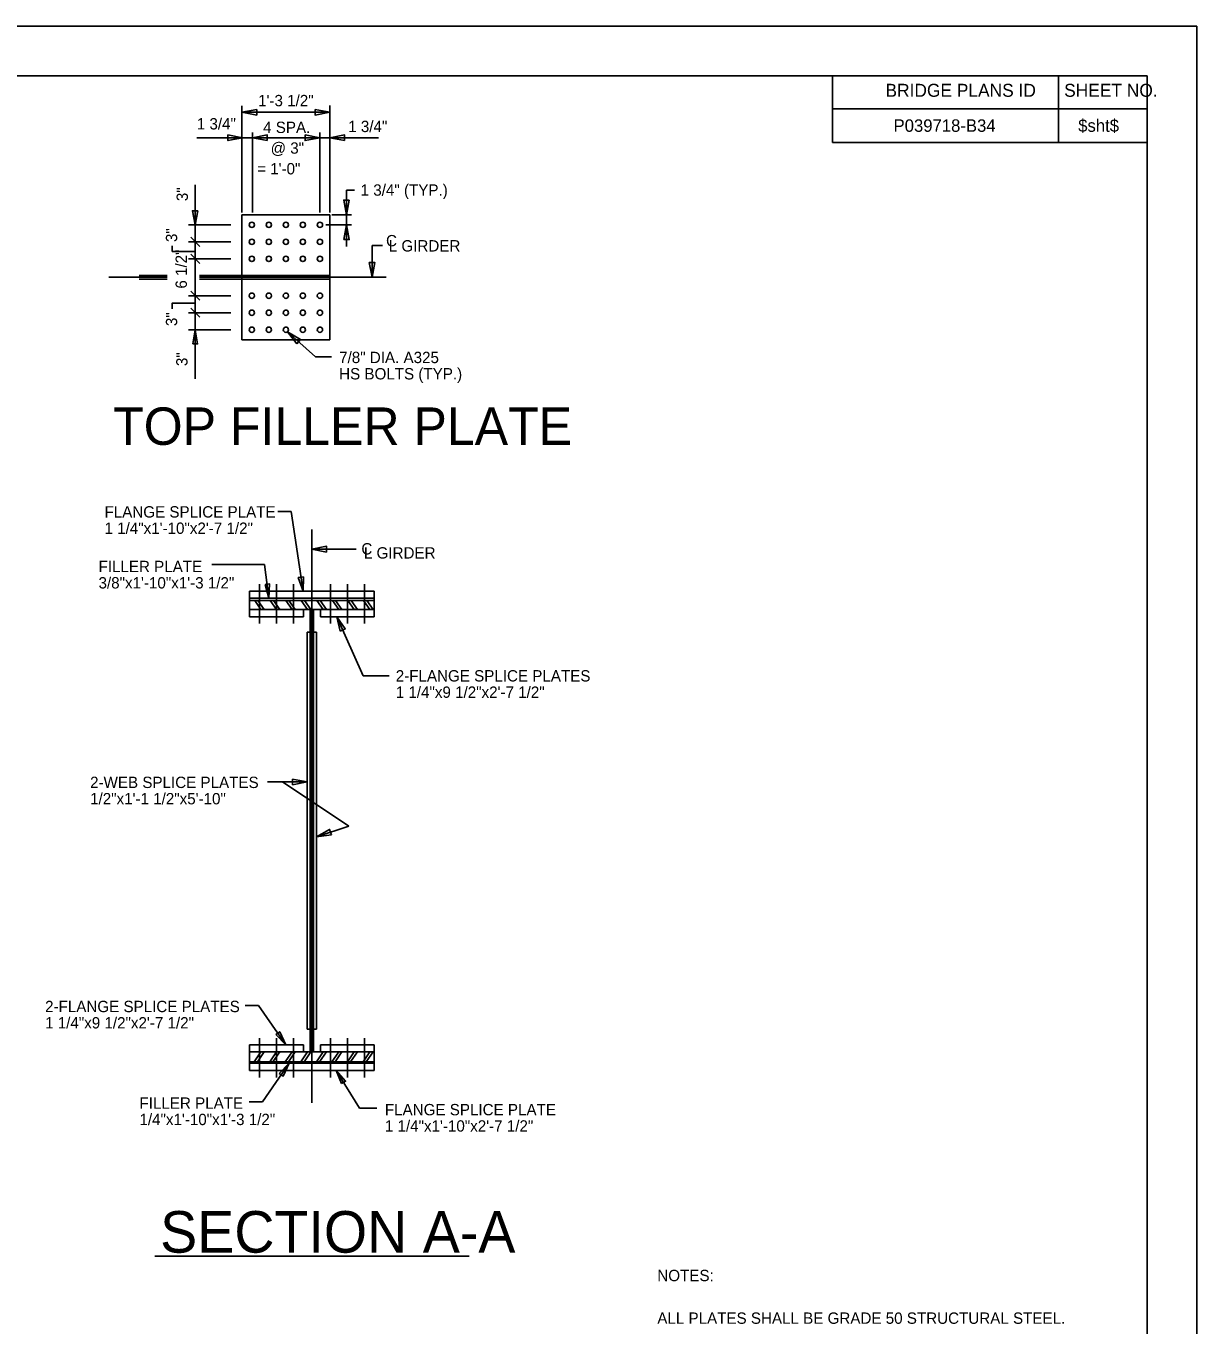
# Model space of a CAD drawing. Extents: x 1970675.2 to 1970715, y 796143 to 796167.2.
# Drawn here: x 1970701.93 to 1970714.84, y 796152.92 to 796167.25 of the extents above; entities that cross this region are included whole.
import ezdxf

# ---------------------------------------------------------------- set-up
doc = ezdxf.new("R2010")
doc.units = 0
for name, color, linetype in [('BR_AUTO DIMENSION', 7, 'Continuous'), ('BR_BORDER LINES', 7, 'Continuous'), ('BR_CENTER LINES', 7, 'Continuous'), ('BR_STRUCTURAL STEEL', 7, 'Continuous'), ('BR_TEXT', 7, 'Continuous'), ('Level 31', 7, 'Continuous')]:
    doc.layers.add(name, color=color, linetype=linetype)

msp = doc.modelspace()

# ---------------------------------------------------------------- linework, layer by layer
at = {"layer": 'BR_AUTO DIMENSION'}
for p, q in [((1970704.309, 796165.191), (1970704.309, 796166.368)), ((1970704.309, 796166.295), (1970705.278, 796166.295)), ((1970705.278, 796165.191), (1970705.278, 796166.372)), ((1970703.813, 796166.015), (1970705.814, 796166.015)), ((1970704.427, 796165.191), (1970704.427, 796166.071)), ((1970705.169, 796165.191), (1970705.169, 796166.071)), ((1970703.794, 796165.497), (1970703.794, 796163.356)), ((1970705.462, 796164.818), (1970705.462, 796165.436)), ((1970705.462, 796165.436), (1970705.549, 796165.436)), ((1970705.301, 796165.164), (1970705.518, 796165.164)), ((1970704.187, 796165.055), (1970703.719, 796165.055)), ((1970705.236, 796165.055), (1970705.518, 796165.055)), ((1970704.187, 796164.868), (1970703.719, 796164.868)), ((1970703.844, 796164.817), (1970703.745, 796164.918)), ((1970703.844, 796164.629), (1970703.745, 796164.731)), ((1970705.744, 796164.829), (1970705.86, 796164.829)), ((1970705.744, 796164.477), (1970705.744, 796164.829)), ((1970704.187, 796164.68), (1970703.719, 796164.68)), ((1970703.844, 796164.223), (1970703.745, 796164.324)), ((1970704.187, 796164.274), (1970703.719, 796164.274)), ((1970703.844, 796164.036), (1970703.745, 796164.137)), ((1970704.187, 796164.086), (1970703.719, 796164.086)), ((1970704.187, 796163.899), (1970703.719, 796163.899)), ((1970705.12, 796163.6), (1970704.812, 796163.876)), ((1970705.12, 796163.6), (1970705.297, 796163.6)), ((1970704.706, 796161.895), (1970704.852, 796161.895)), ((1970704.852, 796161.895), (1970704.983, 796161.018)), ((1970704.56, 796161.311), (1970703.978, 796161.311)), ((1970704.56, 796161.311), (1970704.607, 796160.94)), ((1970705.646, 796160.085), (1970705.354, 796160.736)), ((1970705.933, 796160.085), (1970705.646, 796160.085)), ((1970704.59, 796158.915), (1970705.03, 796158.915)), ((1970704.756, 796158.915), (1970705.489, 796158.429)), ((1970705.489, 796158.429), (1970705.132, 796158.31)), ((1970704.347, 796156.451), (1970704.493, 796156.451)), ((1970704.493, 796156.451), (1970704.794, 796156.018)), ((1970704.535, 796155.389), (1970704.831, 796155.815)), ((1970705.605, 796155.32), (1970705.347, 796155.736)), ((1970704.39, 796155.389), (1970704.535, 796155.389)), ((1970705.798, 796155.32), (1970705.605, 796155.32))]:
    msp.add_line(p, q, dxfattribs=at)
for points in [[(1970704.472, 796166.264), (1970704.309, 796166.295), (1970704.472, 796166.326)], [(1970705.116, 796166.326), (1970705.278, 796166.295), (1970705.116, 796166.264)], [(1970704.155, 796166.046), (1970704.317, 796166.015), (1970704.155, 796165.984)], [(1970704.589, 796165.984), (1970704.427, 796166.015), (1970704.589, 796166.046)], [(1970705.006, 796166.046), (1970705.169, 796166.015), (1970705.006, 796165.984)], [(1970705.441, 796165.984), (1970705.278, 796166.015), (1970705.441, 796166.046)], [(1970705.493, 796165.327), (1970705.462, 796165.164), (1970705.431, 796165.327)], [(1970703.824, 796165.211), (1970703.794, 796165.055), (1970703.764, 796165.211)], [(1970705.431, 796164.893), (1970705.462, 796165.055), (1970705.493, 796164.893)], [(1970705.712, 796164.639), (1970705.744, 796164.477), (1970705.775, 796164.639)], [(1970703.768, 796163.742), (1970703.82, 796163.742), (1970703.794, 796163.899)], [(1970704.913, 796163.744), (1970704.812, 796163.876), (1970704.954, 796163.791)], [(1970705.243, 796161.449), (1970705.081, 796161.48), (1970705.243, 796161.512)], [(1970704.99, 796161.176), (1970704.983, 796161.018), (1970704.93, 796161.167)], [(1970704.564, 796161.092), (1970704.615, 796161.098), (1970704.607, 796160.94)], [(1970705.392, 796160.575), (1970705.354, 796160.736), (1970705.449, 796160.601)], [(1970704.868, 796158.946), (1970705.03, 796158.915), (1970704.868, 796158.884)], [(1970705.296, 796158.331), (1970705.132, 796158.31), (1970705.276, 796158.391)], [(1970704.683, 796156.131), (1970704.726, 796156.161), (1970704.794, 796156.018)], [(1970704.721, 796155.701), (1970704.763, 796155.671), (1970704.831, 796155.815)], [(1970705.407, 796155.59), (1970705.452, 796155.617), (1970705.347, 796155.736)]]:
    msp.add_lwpolyline(points, close=True, dxfattribs=at)
for points in [[(1970703.794, 796164.762), (1970703.541, 796164.762), (1970703.541, 796164.823)], [(1970703.794, 796164.192), (1970703.541, 796164.192), (1970703.541, 796164.131)], [(1970705.081, 796161.48), (1970705.567, 796161.48)]]:
    msp.add_lwpolyline(points, dxfattribs=at)
at = {"layer": 'BR_BORDER LINES'}
for p, q in [((1970714.286, 796166.696), (1970677.253, 796166.696)), ((1970710.818, 796165.963), (1970710.818, 796166.696)), ((1970713.311, 796165.963), (1970713.311, 796166.696)), ((1970714.286, 796143.596), (1970714.286, 796166.696)), ((1970710.818, 796166.334), (1970714.286, 796166.334)), ((1970713.311, 796166.334), (1970714.286, 796166.334)), ((1970714.286, 796165.963), (1970710.818, 796165.963))]:
    msp.add_line(p, q, dxfattribs=at)
at = {"layer": 'BR_CENTER LINES'}
for p, q in [((1970702.843, 796164.477), (1970703.487, 796164.477)), ((1970703.843, 796164.477), (1970705.901, 796164.477)), ((1970705.081, 796161.698), (1970705.081, 796155.379))]:
    msp.add_line(p, q, dxfattribs=at)
at = {"layer": 'BR_STRUCTURAL STEEL'}
for p, q in [((1970704.309, 796163.789), (1970704.309, 796165.164)), ((1970704.309, 796165.164), (1970705.278, 796165.164)), ((1970705.278, 796165.164), (1970705.278, 796163.789)), ((1970703.178, 796164.496), (1970703.487, 796164.496)), ((1970703.178, 796164.457), (1970703.487, 796164.457)), ((1970703.843, 796164.496), (1970705.278, 796164.496)), ((1970703.843, 796164.457), (1970705.278, 796164.457)), ((1970704.309, 796163.789), (1970705.278, 796163.789)), ((1970704.393, 796161.018), (1970705.768, 796161.018)), ((1970704.393, 796160.94), (1970704.393, 796161.018)), ((1970704.503, 796160.663), (1970704.503, 796161.095)), ((1970704.69, 796160.663), (1970704.69, 796161.095)), ((1970704.878, 796160.663), (1970704.878, 796161.095)), ((1970705.284, 796160.663), (1970705.284, 796161.095)), ((1970705.472, 796160.663), (1970705.472, 796161.095)), ((1970705.659, 796160.663), (1970705.659, 796161.095)), ((1970705.768, 796161.018), (1970705.768, 796160.94)), ((1970704.393, 796160.94), (1970705.768, 796160.94)), ((1970704.393, 796160.94), (1970704.393, 796160.916)), ((1970705.768, 796160.94), (1970704.393, 796160.94)), ((1970704.393, 796160.815), (1970704.393, 796160.916)), ((1970704.393, 796160.916), (1970705.768, 796160.916)), ((1970704.393, 796160.916), (1970705.768, 796160.916)), ((1970704.45, 796160.916), (1970704.519, 796160.815)), ((1970704.485, 796160.916), (1970704.555, 796160.815)), ((1970704.621, 796160.916), (1970704.691, 796160.815)), ((1970704.656, 796160.916), (1970704.726, 796160.815)), ((1970704.793, 796160.916), (1970704.862, 796160.815)), ((1970704.828, 796160.916), (1970704.897, 796160.815)), ((1970704.964, 796160.916), (1970705.034, 796160.815)), ((1970704.999, 796160.916), (1970705.069, 796160.815)), ((1970705.135, 796160.916), (1970705.205, 796160.815)), ((1970705.171, 796160.916), (1970705.24, 796160.815)), ((1970705.307, 796160.916), (1970705.376, 796160.815)), ((1970705.342, 796160.916), (1970705.412, 796160.815)), ((1970705.478, 796160.916), (1970705.548, 796160.815)), ((1970705.513, 796160.916), (1970705.583, 796160.815)), ((1970705.65, 796160.916), (1970705.72, 796160.815)), ((1970705.686, 796160.916), (1970705.755, 796160.815)), ((1970705.768, 796160.94), (1970705.768, 796160.916)), ((1970705.768, 796160.815), (1970705.768, 796160.916)), ((1970704.393, 796160.815), (1970704.393, 796160.736)), ((1970704.987, 796160.815), (1970704.393, 796160.815)), ((1970704.393, 796160.815), (1970705.768, 796160.815)), ((1970704.393, 796160.736), (1970704.987, 796160.736)), ((1970704.987, 796160.815), (1970704.987, 796160.736)), ((1970705.061, 796160.815), (1970705.061, 796155.94)), ((1970705.1, 796160.815), (1970705.1, 796155.94)), ((1970705.175, 796160.815), (1970705.768, 796160.815)), ((1970705.175, 796160.815), (1970705.175, 796160.736)), ((1970705.768, 796160.736), (1970705.175, 796160.736)), ((1970705.768, 796160.815), (1970705.768, 796160.736)), ((1970705.061, 796160.565), (1970705.03, 796160.565)), ((1970705.03, 796160.565), (1970705.03, 796156.19)), ((1970705.061, 796156.19), (1970705.061, 796160.565)), ((1970705.1, 796156.19), (1970705.1, 796160.565)), ((1970705.132, 796160.565), (1970705.1, 796160.565)), ((1970705.132, 796160.565), (1970705.132, 796156.19)), ((1970705.061, 796156.19), (1970705.03, 796156.19)), ((1970705.132, 796156.19), (1970705.1, 796156.19)), ((1970704.393, 796155.94), (1970704.393, 796156.018)), ((1970704.393, 796156.018), (1970704.987, 796156.018)), ((1970704.503, 796156.091), (1970704.503, 796155.659)), ((1970704.69, 796156.091), (1970704.69, 796155.659)), ((1970704.878, 796156.091), (1970704.878, 796155.659)), ((1970704.987, 796155.94), (1970704.987, 796156.018)), ((1970705.768, 796156.018), (1970705.175, 796156.018)), ((1970705.175, 796155.94), (1970705.175, 796156.018)), ((1970705.284, 796156.091), (1970705.284, 796155.659)), ((1970705.472, 796156.091), (1970705.472, 796155.659)), ((1970705.659, 796156.091), (1970705.659, 796155.659)), ((1970705.768, 796155.94), (1970705.768, 796156.018)), ((1970704.987, 796155.94), (1970704.393, 796155.94)), ((1970704.393, 796155.94), (1970704.393, 796155.83)), ((1970704.393, 796155.94), (1970705.768, 796155.94)), ((1970705.768, 796155.83), (1970704.393, 796155.83)), ((1970704.393, 796155.83), (1970705.768, 796155.83)), ((1970704.393, 796155.83), (1970704.393, 796155.815)), ((1970704.444, 796155.83), (1970704.519, 796155.94)), ((1970704.48, 796155.83), (1970704.555, 796155.94)), ((1970704.616, 796155.83), (1970704.691, 796155.94)), ((1970704.651, 796155.83), (1970704.726, 796155.94)), ((1970704.787, 796155.83), (1970704.862, 796155.94)), ((1970704.822, 796155.83), (1970704.897, 796155.94)), ((1970704.959, 796155.83), (1970705.034, 796155.94)), ((1970704.994, 796155.83), (1970705.069, 796155.94)), ((1970705.13, 796155.83), (1970705.205, 796155.94)), ((1970705.165, 796155.83), (1970705.24, 796155.94)), ((1970705.175, 796155.94), (1970705.768, 796155.94)), ((1970705.301, 796155.83), (1970705.376, 796155.94)), ((1970705.337, 796155.83), (1970705.412, 796155.94)), ((1970705.473, 796155.83), (1970705.548, 796155.94)), ((1970705.508, 796155.83), (1970705.583, 796155.94)), ((1970705.645, 796155.83), (1970705.72, 796155.94)), ((1970705.68, 796155.83), (1970705.755, 796155.94)), ((1970705.768, 796155.94), (1970705.768, 796155.83)), ((1970705.768, 796155.83), (1970705.768, 796155.815)), ((1970704.393, 796155.815), (1970705.768, 796155.815)), ((1970704.393, 796155.815), (1970704.393, 796155.736)), ((1970705.768, 796155.815), (1970704.393, 796155.815)), ((1970704.393, 796155.736), (1970705.768, 796155.736)), ((1970705.768, 796155.736), (1970705.768, 796155.815))]:
    msp.add_line(p, q, dxfattribs=at)
for centre in [(1970704.419, 796165.055), (1970704.419, 796165.055), (1970704.606, 796165.055), (1970704.606, 796165.055), (1970704.794, 796165.055), (1970704.794, 796165.055), (1970704.981, 796165.055), (1970704.981, 796165.055), (1970705.169, 796165.055), (1970705.169, 796165.055), (1970704.419, 796164.868), (1970704.419, 796164.868), (1970704.606, 796164.868), (1970704.606, 796164.868), (1970704.794, 796164.868), (1970704.794, 796164.868), (1970704.981, 796164.868), (1970704.981, 796164.868), (1970705.169, 796164.868), (1970705.169, 796164.868), (1970704.419, 796164.68), (1970704.419, 796164.68), (1970704.606, 796164.68), (1970704.606, 796164.68), (1970704.794, 796164.68), (1970704.794, 796164.68), (1970704.981, 796164.68), (1970704.981, 796164.68), (1970705.169, 796164.68), (1970705.169, 796164.68), (1970704.419, 796164.274), (1970704.419, 796164.274), (1970704.606, 796164.274), (1970704.606, 796164.274), (1970704.794, 796164.274), (1970704.794, 796164.274), (1970704.981, 796164.274), (1970704.981, 796164.274), (1970705.169, 796164.274), (1970705.169, 796164.274), (1970704.419, 796164.086), (1970704.419, 796164.086), (1970704.606, 796164.086), (1970704.606, 796164.086), (1970704.794, 796164.086), (1970704.794, 796164.086), (1970704.981, 796164.086), (1970704.981, 796164.086), (1970705.169, 796164.086), (1970705.169, 796164.086), (1970704.419, 796163.899), (1970704.419, 796163.899), (1970704.606, 796163.899), (1970704.606, 796163.899), (1970704.794, 796163.899), (1970704.794, 796163.899), (1970704.981, 796163.899), (1970704.981, 796163.899), (1970705.169, 796163.899), (1970705.169, 796163.899)]:
    msp.add_circle(centre, 0.0293, dxfattribs=at)
at = {"layer": 'BR_TEXT'}
msp.add_line((1970703.348, 796153.687), (1970706.814, 796153.687), dxfattribs=at)
at = {"layer": 'Level 31'}
msp.add_line((1970714.836, 796167.246), (1970675.236, 796167.246), dxfattribs=at)
msp.add_lwpolyline([(1970675.236, 796167.246), (1970675.236, 796143.046), (1970714.836, 796143.046), (1970714.836, 796167.246)], dxfattribs=at)

# ---------------------------------------------------------------- texts
at = {"layer": 'BR_TEXT'}
for s, height, p in [('BRIDGE PLANS ID', 0.143, (1970711.403, 796166.466)), ('SHEET NO.', 0.143, (1970713.372, 796166.466)), ('1\'-3 1/2"', 0.125, (1970704.488, 796166.362)), ('1 3/4"', 0.125, (1970703.812, 796166.106)), ('4 SPA. ', 0.125, (1970704.543, 796166.067)), ('1 3/4"', 0.125, (1970705.481, 796166.077)), ('P039718-B34', 0.1375, (1970711.492, 796166.08)), ('$sht$', 0.1375, (1970713.527, 796166.08)), ('@ 3" ', 0.125, (1970704.626, 796165.839)), ('= 1\'-0"', 0.125, (1970704.477, 796165.611)), ('1 3/4" (TYP.)', 0.125, (1970705.618, 796165.376)), ('C', 0.125, (1970705.898, 796164.818)), ('L GIRDER', 0.125, (1970705.928, 796164.761)), ('7/8" DIA. A325', 0.125, (1970705.381, 796163.531)), ('HS BOLTS (TYP.)', 0.125, (1970705.381, 796163.351)), ('TOP FILLER PLATE', 0.4125, (1970702.89, 796162.63)), ('FLANGE SPLICE PLATE', 0.125, (1970702.795, 796161.829)), ('1 1/4"x1\'-10"x2\'-7 1/2"', 0.125, (1970702.795, 796161.649)), ('C', 0.125, (1970705.626, 796161.422)), ('L GIRDER', 0.125, (1970705.654, 796161.377)), ('FILLER PLATE', 0.125, (1970702.729, 796161.227)), ('3/8"x1\'-10"x1\'-3 1/2"', 0.125, (1970702.729, 796161.047)), ('2-FLANGE SPLICE PLATES', 0.125, (1970706.005, 796160.022)), ('1 1/4"x9 1/2"x2\'-7 1/2"', 0.125, (1970706.005, 796159.842)), ('2-WEB SPLICE PLATES', 0.125, (1970702.636, 796158.848)), ('1/2"x1\'-1 1/2"x5\'-10"', 0.125, (1970702.636, 796158.668)), ('2-FLANGE SPLICE PLATES', 0.125, (1970702.14, 796156.378)), ('1 1/4"x9 1/2"x2\'-7 1/2"', 0.125, (1970702.14, 796156.198)), ('FILLER PLATE', 0.125, (1970703.18, 796155.313)), ('1/4"x1\'-10"x1\'-3 1/2"', 0.125, (1970703.18, 796155.133)), ('FLANGE SPLICE PLATE', 0.125, (1970705.885, 796155.241)), ('1 1/4"x1\'-10"x2\'-7 1/2"', 0.125, (1970705.885, 796155.061)), ('SECTION A-A', 0.45834, (1970703.408, 796153.727)), ('NOTES:', 0.125, (1970708.888, 796153.413)), ('ALL PLATES SHALL BE GRADE 50 STRUCTURAL STEEL.', 0.125, (1970708.888, 796152.943))]:
    msp.add_text(s, height=height, dxfattribs=at).set_placement(p)
for s, p in [('3"', (1970703.714, 796165.316)), ('3"', (1970703.596, 796164.865)), ('6 1/2"', (1970703.703, 796164.352)), ('3"', (1970703.596, 796163.939)), ('3"', (1970703.71, 796163.498))]:
    msp.add_text(s, height=0.125, rotation=90, dxfattribs=at).set_placement(p)

doc.saveas('drawing.dxf')
